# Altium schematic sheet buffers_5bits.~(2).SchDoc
size A4
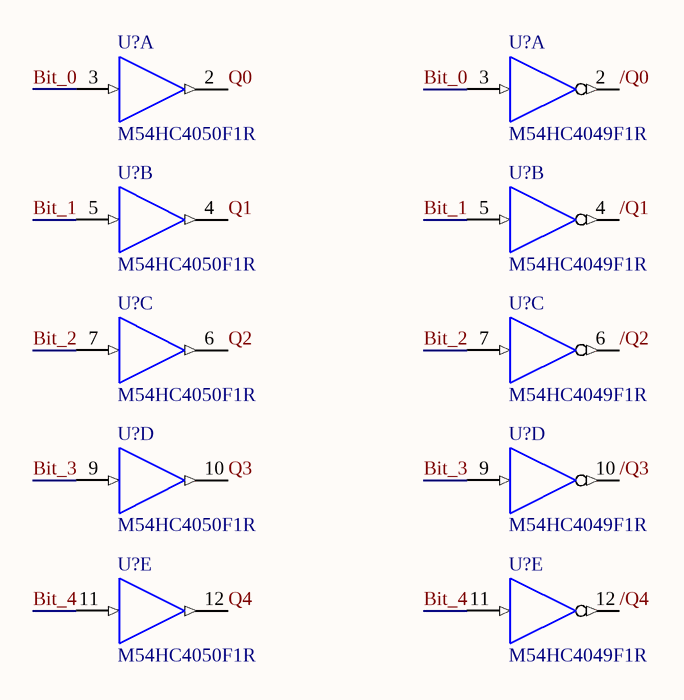
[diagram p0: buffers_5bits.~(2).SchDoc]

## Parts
(Parts that share a designator on the sheet are numbered #1, #2 ... from top to bottom, then left to right.)
U?#1  M54HC4050F1R  [DIP16]  (part A of 6)
U?#2  M54HC4049F1R  [DIP16]  (part A of 6)
U?#3  M54HC4050F1R  [DIP16]  (part B of 6)
U?#4  M54HC4049F1R  [DIP16]  (part B of 6)
U?#5  M54HC4050F1R  [DIP16]  (part C of 6)
U?#6  M54HC4049F1R  [DIP16]  (part C of 6)
U?#7  M54HC4050F1R  [DIP16]  (part D of 6)
U?#8  M54HC4049F1R  [DIP16]  (part D of 6)
U?#9  M54HC4050F1R  [DIP16]  (part E of 6)
U?#10  M54HC4049F1R  [DIP16]  (part E of 6)

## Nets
GND: U?#1.8(GND) U?#2.8(GND) U?#3.8(GND) U?#4.8(GND) U?#5.8(GND) U?#6.8(GND) U?#7.8(GND) U?#8.8(GND) U?#9.8(GND) U?#10.8(GND)
VCC: U?#1.1(VCC) U?#2.1(VCC) U?#3.1(VCC) U?#4.1(VCC) U?#5.1(VCC) U?#6.1(VCC) U?#7.1(VCC) U?#8.1(VCC) U?#9.1(VCC) U?#10.1(VCC)
/Q0: U?#2.2(Y)
/Q1: U?#4.4(Y)
/Q2: U?#6.6(Y)
/Q3: U?#8.10(Y)
/Q4: U?#10.12(Y)
Bit_0: U?#1.3(A) U?#2.3(A)
Bit_1: U?#3.5(A) U?#4.5(A)
Bit_2: U?#5.7(A) U?#6.7(A)
Bit_3: U?#7.9(A) U?#8.9(A)
Bit_4: U?#9.11(A) U?#10.11(A)
Q0: U?#1.2(Y)
Q1: U?#3.4(Y)
Q2: U?#5.6(Y)
Q3: U?#7.10(Y)
Q4: U?#9.12(Y)

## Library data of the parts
U?#1 U?#3 U?#5 U?#7 U?#9 = M54HC4050F1R: Hex Buffer/Converter Non-Inverting; Note: Pins 13 and 16 are not connected and not drawn.
U?#2 U?#4 U?#6 U?#8 U?#10 = M54HC4049F1R: Hex Buffer/Converter Invertering; Note: Pins 13 and 16 are not connected and not drawn.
